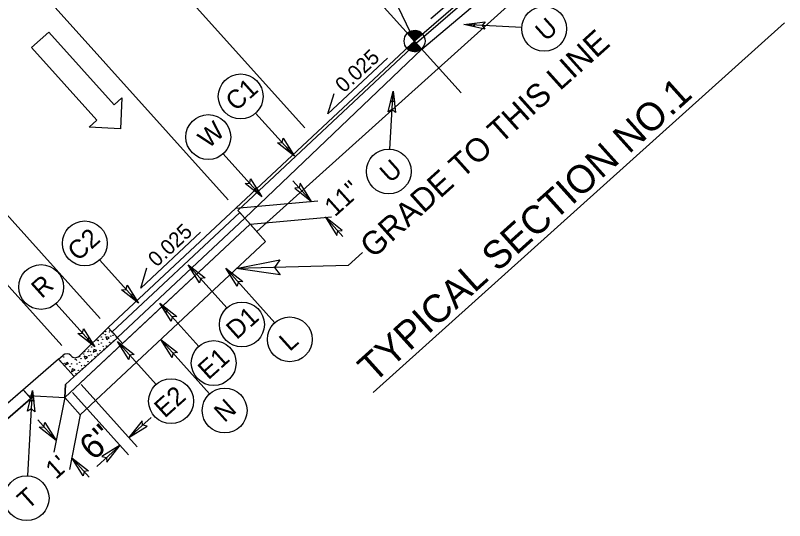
# Model space of a CAD drawing. Extents: x 2488411 to 2488707, y 383669 to 383962.
# Drawn here: x 2488564.63 to 2488597.63, y 383847.24 to 383868.92 of the extents above; entities that cross this region are included whole.
import ezdxf

# ---------------------------------------------------------------- set-up
doc = ezdxf.new("R2010")
doc.units = 0
for name, color, linetype in [('Old_Level_44', 7, 'Continuous'), ('Prop Dimension', 7, 'Continuous'), ('Prop DSN Text', 7, 'Continuous'), ('Prop Paint Stripe', 7, 'Continuous'), ('Prop Rip Rap Related Quantities Text', 7, 'Continuous'), ('Prop Roadway Profile Bench Mark Info Text', 7, 'Continuous'), ('Prop ROW RW Lines', 7, 'Continuous'), ('Prop Vertical Profile Curve Label', 7, 'Continuous'), ('Sheet Data Field CELL', 7, 'Continuous'), ('Sheet Data Text CELL', 7, 'Continuous'), ('Sheet Profile Grid Major CELL', 7, 'Continuous'), ('Sheet Sticker Preliminary CELL', 7, 'Continuous'), ('Sheet Symbology CELL', 7, 'Continuous'), ('Sheet Title CELL', 7, 'Continuous'), ('Typical ID Circle CELL', 7, 'Continuous'), ('Typical Terminator CELL', 7, 'Continuous'), ('Typical Text Centerline CELL', 7, 'Continuous'), ('Typical Text ID Circle CELL', 7, 'Continuous')]:
    doc.layers.add(name, color=color, linetype=linetype)

msp = doc.modelspace()

# ---------------------------------------------------------------- linework, layer by layer
at = {"layer": 'Prop Dimension'}
for p, q in [((2488580.003, 383871.462), (2488581.754, 383867.821)), ((2488578.9, 383858.187), (2488579.514, 383858.74)), ((2488578.9, 383858.187), (2488574.105, 383858.054))]:
    msp.add_line(p, q, dxfattribs=at)
at = {"layer": 'Prop DSN Text'}
for p, q in [((2488586.354, 383868.399), (2488583.872, 383868.53)), ((2488580.698, 383863.186), (2488580.831, 383865.669)), ((2488574.936, 383864.73), (2488576.597, 383862.881)), ((2488573.545, 383862.986), (2488575.207, 383861.138)), ((2488568.248, 383858.422), (2488569.909, 383856.574)), ((2488573.704, 383856.372), (2488572.042, 383858.221)), ((2488575.758, 383855.735), (2488573.657, 383858.072)), ((2488566.373, 383856.55), (2488568.035, 383854.702)), ((2488572.492, 383854.718), (2488570.83, 383856.567)), ((2488570.664, 383853.082), (2488569.002, 383854.93)), ((2488572.962, 383852.681), (2488570.861, 383855.019)), ((2488565.16, 383849.163), (2488565.356, 383852.822))]:
    msp.add_line(p, q, dxfattribs=at)
for centre in [(2488587.314, 383868.347), (2488574.293, 383865.445), (2488572.903, 383863.701), (2488580.647, 383862.226), (2488567.605, 383859.137), (2488565.73, 383857.265), (2488574.347, 383855.657), (2488576.401, 383855.02), (2488573.135, 383854.003), (2488571.306, 383852.367), (2488573.605, 383851.966), (2488565.11, 383848.203)]:
    msp.add_circle(centre, 0.962, dxfattribs=at)
at = {"layer": 'Prop Paint Stripe'}
for points in [[(2488584.763, 383868.328), (2488583.872, 383868.53), (2488584.784, 383868.642), (2488584.661, 383868.488)], [(2488580.628, 383864.778), (2488580.831, 383865.669), (2488580.942, 383864.756), (2488580.788, 383864.88)], [(2488576.111, 383863.654), (2488576.597, 383862.881), (2488575.873, 383863.447), (2488576.069, 383863.469)], [(2488574.721, 383861.911), (2488575.207, 383861.138), (2488574.483, 383861.704), (2488574.679, 383861.725)], [(2488576.61, 383861.501), (2488577.327, 383860.935), (2488576.841, 383861.715), (2488576.799, 383861.523)], [(2488578.652, 383859.693), (2488577.935, 383860.259), (2488578.421, 383859.479), (2488578.463, 383859.671)], [(2488572.529, 383857.448), (2488572.042, 383858.221), (2488572.766, 383857.655), (2488572.57, 383857.633)], [(2488574.143, 383857.299), (2488573.657, 383858.072), (2488574.381, 383857.506), (2488574.185, 383857.485)], [(2488569.423, 383857.347), (2488569.909, 383856.574), (2488569.185, 383857.14), (2488569.381, 383857.161)], [(2488571.317, 383855.794), (2488570.83, 383856.567), (2488571.554, 383856.001), (2488571.358, 383855.979)], [(2488567.548, 383855.475), (2488568.035, 383854.702), (2488567.311, 383855.268), (2488567.506, 383855.29)], [(2488569.489, 383854.157), (2488569.002, 383854.93), (2488569.726, 383854.364), (2488569.53, 383854.342)], [(2488571.348, 383854.246), (2488570.861, 383855.019), (2488571.585, 383854.452), (2488571.389, 383854.431)], [(2488565.153, 383851.932), (2488565.356, 383852.822), (2488565.467, 383851.91), (2488565.314, 383852.034)], [(2488570.06, 383851.525), (2488569.494, 383850.808), (2488570.274, 383851.294), (2488570.081, 383851.336)], [(2488565.891, 383851.454), (2488566.378, 383850.681), (2488565.654, 383851.247), (2488565.85, 383851.268)], [(2488568.556, 383849.756), (2488569.122, 383850.473), (2488568.342, 383849.987), (2488568.535, 383849.945)], [(2488567.533, 383849.164), (2488567.046, 383849.937), (2488567.77, 383849.371), (2488567.574, 383849.349)]]:
    msp.add_lwpolyline(points, close=True, dxfattribs=at)
at = {"layer": 'Prop Rip Rap Related Quantities Text'}
for p, q in [((2488589.787, 383874.592), (2488581.836, 383867.727)), ((2488586.294, 383871.741), (2488581.754, 383867.821)), ((2488574.168, 383860.551), (2488581.84, 383867.73)), ((2488577.375, 383863.723), (2488581.754, 383867.821)), ((2488568.614, 383855.525), (2488577.375, 383863.723)), ((2488568.781, 383855.339), (2488574.253, 383860.46)), ((2488574.474, 383860.214), (2488574.17, 383860.553)), ((2488569.002, 383855.094), (2488574.474, 383860.214)), ((2488566.744, 383852.528), (2488574.695, 383859.969)), ((2488574.695, 383859.969), (2488575.363, 383859.225)), ((2488567.412, 383851.785), (2488575.363, 383859.225)), ((2488569.004, 383855.091), (2488569.223, 383854.848)), ((2488567.145, 383853.42), (2488566.773, 383853.086)), ((2488566.744, 383852.528), (2488566.773, 383853.086)), ((2488565.183, 383852.612), (2488566.744, 383852.528)), ((2488566.744, 383852.528), (2488567.412, 383851.785))]:
    msp.add_line(p, q, dxfattribs=at)
at = {"layer": 'Prop Roadway Profile Bench Mark Info Text'}
for p, q in [((2488585.092, 383871.053), (2488582.452, 383868.775)), ((2488578.037, 383864.696), (2488580.596, 383867.091)), ((2488578.037, 383864.696), (2488578.303, 383865.572)), ((2488570.004, 383857.218), (2488572.563, 383859.613)), ((2488570.004, 383857.218), (2488570.27, 383858.094))]:
    msp.add_line(p, q, dxfattribs=at)
at = {"layer": 'Prop ROW RW Lines'}
for p, q in [((2488565.318, 383867.543), (2488566.055, 383868.205)), ((2488566.055, 383868.205), (2488568.862, 383865.082)), ((2488568.126, 383864.42), (2488565.318, 383867.543)), ((2488568.862, 383865.082), (2488569.197, 383865.382)), ((2488569.197, 383865.382), (2488569.137, 383864.058)), ((2488567.792, 383864.119), (2488568.126, 383864.42)), ((2488569.137, 383864.058), (2488567.792, 383864.119))]:
    msp.add_line(p, q, dxfattribs=at)
at = {"layer": 'Prop Vertical Profile Curve Label'}
msp.add_line((2488566.477, 383854.164), (2488560.797, 383849.268), dxfattribs=at)
at = {"layer": 'Sheet Data Field CELL'}
for p, q in [((2488574.252, 383860.458), (2488568.781, 383855.339)), ((2488574.474, 383860.214), (2488574.252, 383860.458)), ((2488569.002, 383855.094), (2488574.474, 383860.214)), ((2488568.781, 383855.339), (2488569.002, 383855.094))]:
    msp.add_line(p, q, dxfattribs=at)
at = {"layer": 'Sheet Data Text CELL'}
msp.add_line((2488579.979, 383852.736), (2488597.63, 383868.603), dxfattribs=at)
at = {"layer": 'Sheet Profile Grid Major CELL'}
for p, q in [((2488564.962, 383852.858), (2488561.173, 383849.593)), ((2488565.296, 383852.486), (2488564.962, 383852.858)), ((2488565.275, 383852.468), (2488565.283, 383852.501)), ((2488565.296, 383852.486), (2488561.508, 383849.221)), ((2488561.508, 383849.221), (2488565.275, 383852.468))]:
    msp.add_line(p, q, dxfattribs=at)
msp.add_lwpolyline([(2488565.283, 383852.501), (2488565.183, 383852.612), (2488564.962, 383852.858)], dxfattribs=at)
at = {"layer": 'Sheet Sticker Preliminary CELL'}
for points in [[(2488584.336, 383868.425), (2488583.872, 383868.53), (2488584.347, 383868.589), (2488584.283, 383868.508)], [(2488580.725, 383865.205), (2488580.831, 383865.669), (2488580.889, 383865.194), (2488580.809, 383865.258)], [(2488576.344, 383863.284), (2488576.597, 383862.881), (2488576.22, 383863.176), (2488576.322, 383863.187)], [(2488574.954, 383861.54), (2488575.207, 383861.138), (2488574.83, 383861.433), (2488574.932, 383861.444)], [(2488575.988, 383857.783), (2488574.105, 383858.054), (2488575.98, 383858.439), (2488575.75, 383858.1)], [(2488569.656, 383856.976), (2488569.909, 383856.574), (2488569.532, 383856.869), (2488569.634, 383856.88)], [(2488571.084, 383856.164), (2488570.83, 383856.567), (2488571.207, 383856.272), (2488571.105, 383856.261)], [(2488567.781, 383855.105), (2488568.035, 383854.702), (2488567.658, 383854.997), (2488567.76, 383855.008)], [(2488565.25, 383852.359), (2488565.356, 383852.822), (2488565.414, 383852.347), (2488565.334, 383852.412)]]:
    msp.add_lwpolyline(points, close=True, dxfattribs=at)
at = {"layer": 'Sheet Symbology CELL'}
for p, q in [((2488582.065, 383867.476), (2488590.091, 383874.253)), ((2488574.474, 383860.214), (2488582.065, 383867.476)), ((2488574.168, 383860.551), (2488574.252, 383860.458)), ((2488574.253, 383860.46), (2488574.474, 383860.214)), ((2488574.474, 383860.214), (2488569.002, 383855.094)), ((2488574.695, 383859.969), (2488574.474, 383860.214)), ((2488566.744, 383852.528), (2488569.223, 383854.848)), ((2488569.002, 383855.094), (2488569.004, 383855.091)), ((2488569.004, 383855.091), (2488569.223, 383854.848)), ((2488569.223, 383854.848), (2488569.004, 383855.091)), ((2488567.907, 383854.105), (2488567.145, 383853.42)), ((2488567.145, 383853.42), (2488566.773, 383853.086)), ((2488566.773, 383853.086), (2488566.744, 383852.528))]:
    msp.add_line(p, q, dxfattribs=at)
for points in [[(2488589.787, 383874.592), (2488581.84, 383867.73), (2488581.838, 383867.728)], [(2488581.838, 383867.728), (2488581.836, 383867.727), (2488574.168, 383860.551)], [(2488574.252, 383860.458), (2488574.253, 383860.46)], [(2488569.223, 383854.848), (2488571.847, 383857.304), (2488574.695, 383859.969)], [(2488568.836, 383854.94), (2488567.915, 383854.112), (2488567.915, 383854.112)], [(2488569.004, 383855.091), (2488568.844, 383854.947), (2488568.844, 383854.947)]]:
    msp.add_lwpolyline(points, dxfattribs=at)
for centre in [(2488568.836, 383854.948), (2488567.907, 383854.113)]:
    msp.add_arc(centre, 0.00802, 270.1633, 353.7444, dxfattribs=at)
at = {"layer": 'Sheet Title CELL'}
for p, q in [((2488577.04, 383864.096), (2488569.694, 383872.267)), ((2488568.264, 383855.915), (2488555.219, 383870.426)), ((2488573.76, 383861.008), (2488565.32, 383870.397)), ((2488566.613, 383854.761), (2488555.55, 383867.066)), ((2488577.327, 383860.935), (2488576.532, 383861.82)), ((2488574.086, 383860.646), (2488577.604, 383860.96)), ((2488574.695, 383859.969), (2488578.192, 383860.282)), ((2488578.682, 383859.428), (2488577.935, 383860.259)), ((2488569.858, 383850.403), (2488567.452, 383853.079)), ((2488566.744, 383852.528), (2488566.278, 383850.175)), ((2488569.486, 383850.069), (2488567.08, 383852.745)), ((2488566.378, 383850.681), (2488565.583, 383851.565)), ((2488567.412, 383851.785), (2488566.946, 383849.432)), ((2488570.446, 383851.663), (2488569.494, 383850.808)), ((2488569.122, 383850.473), (2488568.117, 383849.57)), ((2488567.793, 383849.106), (2488567.046, 383849.937))]:
    msp.add_line(p, q, dxfattribs=at)
at = {"layer": 'Typical ID Circle CELL'}
for p, q in [((2488568.614, 383855.525), (2488567.361, 383854.301)), ((2488569.004, 383855.091), (2488568.614, 383855.525)), ((2488567.145, 383853.42), (2488569.004, 383855.091)), ((2488568.65, 383855.096), (2488568.506, 383855.127)), ((2488568.506, 383855.127), (2488568.556, 383855.019)), ((2488568.556, 383855.019), (2488568.65, 383855.096)), ((2488567.992, 383854.589), (2488567.966, 383854.465)), ((2488567.966, 383854.465), (2488568.115, 383854.546)), ((2488568.115, 383854.546), (2488567.992, 383854.589)), ((2488566.477, 383854.164), (2488566.67, 383854.338)), ((2488567.145, 383853.42), (2488566.477, 383854.164)), ((2488567.016, 383854.312), (2488567.009, 383854.32)), ((2488567.721, 383854.26), (2488567.577, 383854.292)), ((2488567.577, 383854.292), (2488567.628, 383854.185)), ((2488567.628, 383854.185), (2488567.721, 383854.26)), ((2488566.757, 383853.907), (2488566.841, 383854.044)), ((2488566.89, 383853.965), (2488566.757, 383853.907)), ((2488566.841, 383854.044), (2488566.89, 383853.965)), ((2488567.063, 383853.754), (2488567.037, 383853.63)), ((2488567.037, 383853.63), (2488567.187, 383853.711)), ((2488567.187, 383853.711), (2488567.063, 383853.754))]:
    msp.add_line(p, q, dxfattribs=at)
for centre in [(2488568.389, 383855.266), (2488568.491, 383855.221), (2488568.506, 383855.349), (2488568.67, 383855.329), (2488568.689, 383855.392), (2488568.718, 383855.156), (2488568.766, 383855.331), (2488568.82, 383855.187), (2488567.96, 383854.804), (2488568.132, 383854.997), (2488568.178, 383854.971), (2488568.201, 383854.8), (2488568.314, 383854.863), (2488568.32, 383855.12), (2488568.367, 383855.026), (2488568.671, 383854.892), (2488568.836, 383854.948), (2488568.977, 383855.106), (2488567.598, 383854.491), (2488567.741, 383854.494), (2488567.76, 383854.557), (2488567.838, 383854.496), (2488567.904, 383854.686), (2488568.252, 383854.531), (2488568.392, 383854.725), (2488568.425, 383854.602), (2488568.534, 383854.738), (2488566.699, 383854.262), (2488567.203, 383854.162), (2488567.391, 383854.285), (2488567.438, 383854.191), (2488567.562, 383854.386), (2488567.789, 383854.321), (2488567.891, 383854.352), (2488568.048, 383854.271), (2488568.151, 383854.386), (2488566.56, 383854.091), (2488566.721, 383853.99), (2488566.975, 383853.851), (2488567.031, 383853.969), (2488567.249, 383854.136), (2488567.273, 383853.965), (2488567.385, 383854.028), (2488567.463, 383853.89), (2488567.605, 383853.903), (2488567.742, 383854.057), (2488567.907, 383854.113), (2488567.222, 383853.551), (2488567.323, 383853.695), (2488567.496, 383853.767)]:
    msp.add_circle(centre, 0.00802, dxfattribs=at)
for centre, start, end in [((2488566.831, 383854.16), 41.9538, 131.9538), ((2488567.194, 383854.472), 221.9538, 314.3383)]:
    msp.add_arc(centre, 0.24, start, end, dxfattribs=at)
at = {"layer": 'Typical Terminator CELL'}
msp.add_line((2488583.758, 383865.593), (2488574.09, 383876.348), dxfattribs=at)
at = {"layer": 'Typical Text Centerline CELL'}
for p, q in [((2488581.456, 383868.155), (2488581.754, 383867.821)), ((2488581.754, 383867.821), (2488581.456, 383868.155)), ((2488582.087, 383868.121), (2488581.754, 383867.821)), ((2488581.422, 383867.522), (2488581.754, 383867.821)), ((2488581.754, 383867.821), (2488582.054, 383867.489))]:
    msp.add_line(p, q, dxfattribs=at)
for points in [[(2488581.76, 383867.826), (2488581.46, 383868.159), (2488581.46, 383868.159)], [(2488581.766, 383867.832), (2488581.467, 383868.165)], [(2488581.773, 383867.838), (2488581.474, 383868.17)], [(2488581.78, 383867.844), (2488581.481, 383868.176)], [(2488581.786, 383867.85), (2488581.488, 383868.181)], [(2488581.793, 383867.856), (2488581.496, 383868.187)], [(2488581.8, 383867.862), (2488581.503, 383868.192)], [(2488581.806, 383867.868), (2488581.511, 383868.196)], [(2488581.813, 383867.874), (2488581.518, 383868.202)], [(2488581.82, 383867.88), (2488581.526, 383868.206)], [(2488581.826, 383867.886), (2488581.534, 383868.211)], [(2488581.833, 383867.892), (2488581.542, 383868.215)], [(2488581.84, 383867.898), (2488581.55, 383868.22)], [(2488581.846, 383867.904), (2488581.559, 383868.223)], [(2488581.853, 383867.91), (2488581.567, 383868.228)], [(2488581.86, 383867.916), (2488581.576, 383868.232)], [(2488581.866, 383867.922), (2488581.584, 383868.235)], [(2488581.873, 383867.928), (2488581.593, 383868.239)], [(2488581.88, 383867.934), (2488581.602, 383868.242)], [(2488581.886, 383867.94), (2488581.612, 383868.245)], [(2488581.893, 383867.946), (2488581.621, 383868.248)], [(2488581.899, 383867.952), (2488581.63, 383868.251)], [(2488581.906, 383867.958), (2488581.639, 383868.254)], [(2488581.913, 383867.964), (2488581.649, 383868.257)], [(2488581.919, 383867.97), (2488581.659, 383868.259)], [(2488581.926, 383867.976), (2488581.669, 383868.261)], [(2488581.933, 383867.982), (2488581.68, 383868.263)], [(2488581.939, 383867.988), (2488581.691, 383868.264)], [(2488581.946, 383867.994), (2488581.701, 383868.266)], [(2488581.953, 383868), (2488581.712, 383868.267)], [(2488581.959, 383868.006), (2488581.723, 383868.268)], [(2488581.966, 383868.012), (2488581.735, 383868.269)], [(2488581.973, 383868.018), (2488581.747, 383868.269)], [(2488581.979, 383868.024), (2488581.759, 383868.269)], [(2488581.986, 383868.03), (2488581.771, 383868.269)], [(2488581.993, 383868.036), (2488581.783, 383868.268)], [(2488581.999, 383868.041), (2488581.797, 383868.267)], [(2488582.006, 383868.047), (2488581.81, 383868.266)], [(2488582.013, 383868.053), (2488581.824, 383868.264)], [(2488582.019, 383868.059), (2488581.838, 383868.261)], [(2488582.026, 383868.065), (2488581.852, 383868.258)], [(2488582.033, 383868.071), (2488581.868, 383868.255)], [(2488582.039, 383868.077), (2488581.884, 383868.25)], [(2488582.046, 383868.083), (2488581.901, 383868.245)], [(2488582.053, 383868.089), (2488581.919, 383868.238)], [(2488582.059, 383868.095), (2488581.938, 383868.23)], [(2488582.066, 383868.101), (2488581.959, 383868.22)], [(2488582.073, 383868.107), (2488581.983, 383868.206)], [(2488582.079, 383868.113), (2488582.011, 383868.189)], [(2488582.086, 383868.119), (2488582.053, 383868.156)], [(2488581.862, 383867.387), (2488581.598, 383867.681)], [(2488581.872, 383867.39), (2488581.605, 383867.687)], [(2488581.882, 383867.393), (2488581.612, 383867.693)], [(2488581.891, 383867.396), (2488581.618, 383867.699)], [(2488581.9, 383867.399), (2488581.625, 383867.705)], [(2488581.91, 383867.402), (2488581.632, 383867.711)], [(2488581.919, 383867.405), (2488581.638, 383867.717)], [(2488581.928, 383867.409), (2488581.645, 383867.723)], [(2488581.936, 383867.412), (2488581.652, 383867.729)], [(2488581.945, 383867.416), (2488581.658, 383867.735)], [(2488581.953, 383867.421), (2488581.665, 383867.741)], [(2488581.962, 383867.424), (2488581.672, 383867.747)], [(2488581.97, 383867.429), (2488581.678, 383867.753)], [(2488581.978, 383867.433), (2488581.685, 383867.759)], [(2488581.986, 383867.438), (2488581.692, 383867.765)], [(2488581.994, 383867.442), (2488581.698, 383867.771)], [(2488582.001, 383867.448), (2488581.705, 383867.777)], [(2488582.008, 383867.453), (2488581.712, 383867.783)], [(2488582.015, 383867.458), (2488581.718, 383867.789)], [(2488582.023, 383867.463), (2488581.725, 383867.795)], [(2488582.03, 383867.469), (2488581.732, 383867.801)], [(2488582.037, 383867.475), (2488581.738, 383867.807)], [(2488582.044, 383867.48), (2488581.745, 383867.813)], [(2488582.051, 383867.486), (2488582.051, 383867.486), (2488581.752, 383867.819)], [(2488581.468, 383867.478), (2488581.425, 383867.525)], [(2488581.505, 383867.45), (2488581.432, 383867.531)], [(2488581.532, 383867.433), (2488581.439, 383867.537)], [(2488581.556, 383867.421), (2488581.445, 383867.543)], [(2488581.576, 383867.411), (2488581.452, 383867.549)], [(2488581.596, 383867.403), (2488581.459, 383867.555)], [(2488581.613, 383867.397), (2488581.465, 383867.561)], [(2488581.629, 383867.392), (2488581.472, 383867.567)], [(2488581.645, 383867.388), (2488581.479, 383867.573)], [(2488581.661, 383867.384), (2488581.485, 383867.579)], [(2488581.675, 383867.381), (2488581.492, 383867.585)], [(2488581.689, 383867.379), (2488581.499, 383867.591)], [(2488581.703, 383867.377), (2488581.505, 383867.597)], [(2488581.717, 383867.375), (2488581.512, 383867.603)], [(2488581.729, 383867.375), (2488581.519, 383867.609)], [(2488581.742, 383867.374), (2488581.525, 383867.615)], [(2488581.754, 383867.374), (2488581.532, 383867.621)], [(2488581.766, 383867.374), (2488581.538, 383867.627)], [(2488581.778, 383867.374), (2488581.545, 383867.633)], [(2488581.789, 383867.375), (2488581.552, 383867.639)], [(2488581.8, 383867.377), (2488581.558, 383867.645)], [(2488581.811, 383867.377), (2488581.565, 383867.651)], [(2488581.822, 383867.379), (2488581.572, 383867.657)], [(2488581.832, 383867.381), (2488581.578, 383867.663)], [(2488581.842, 383867.383), (2488581.585, 383867.669)], [(2488581.852, 383867.385), (2488581.592, 383867.675)]]:
    msp.add_lwpolyline(points, dxfattribs=at)
msp.add_circle((2488581.755, 383867.822), 0.448, dxfattribs=at)
for start, end in [(41.9443, 131.9443), (221.9443, 311.9443)]:
    msp.add_arc((2488581.755, 383867.822), 0.448, start, end, dxfattribs=at)
at = {"layer": 'Typical Text ID Circle CELL'}
for p, q in [((2488582.065, 383867.476), (2488590.091, 383874.253)), ((2488574.979, 383859.652), (2488590.597, 383873.691)), ((2488574.474, 383860.214), (2488582.065, 383867.476)), ((2488574.979, 383859.652), (2488574.474, 383860.214))]:
    msp.add_line(p, q, dxfattribs=at)

# ---------------------------------------------------------------- texts
at = {"layer": 'Old_Level_44'}
for s, p in [('U', (2488587.383, 383867.776)), ('C1', (2488574.089, 383864.775)), ('W', (2488572.91, 383863.175)), ('U', (2488580.709, 383861.695)), ('C2', (2488567.311, 383858.34)), ('R', (2488565.758, 383856.741)), ('D1', (2488574.12, 383854.978)), ('L', (2488576.393, 383854.47)), ('E1', (2488572.904, 383853.253)), ('E2', (2488571.033, 383851.613)), ('N', (2488573.597, 383851.416)), ('T', (2488565.159, 383847.683))]:
    msp.add_text(s, height=0.8, rotation=41.9538, dxfattribs=at).set_placement(p)
at = {"layer": 'Prop Dimension'}
msp.add_text('GRADE TO THIS LINE', height=1, rotation=41.9538, dxfattribs=at).set_placement((2488579.979, 383858.46))
at = {"layer": 'Prop Roadway Profile Bench Mark Info Text'}
for p in [(2488578.72, 383865.57), (2488570.687, 383858.092)]:
    msp.add_text('0.025', height=0.6476, rotation=43.0996, dxfattribs=at).set_placement(p)
at = {"layer": 'Sheet Data Text CELL'}
msp.add_text('TYPICAL SECTION NO.1  ', height=1.2, rotation=41.9538, dxfattribs=at).set_placement((2488580.008, 383853.113))
at = {"layer": 'Sheet Title CELL'}
for s, height, p in [('11"', 0.8, (2488578.335, 383860.252)), ('6"', 1.0817, (2488567.979, 383849.779)), ("1'", 0.8, (2488566.365, 383848.978))]:
    msp.add_text(s, height=height, rotation=41.9538, dxfattribs=at).set_placement(p)

doc.saveas('drawing.dxf')
